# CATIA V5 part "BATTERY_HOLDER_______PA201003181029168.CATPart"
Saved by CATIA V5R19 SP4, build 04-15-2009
Part number: BATTERY_HOLDER_______PA201003181029168
Bounding box of the stored display mesh (mm): x -13 to 13, y -8 to 8, z -29 to 29
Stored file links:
  E:\CadInnWork\1\BATTERY_HOLDER_______PA201003181029168.CATPart
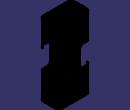
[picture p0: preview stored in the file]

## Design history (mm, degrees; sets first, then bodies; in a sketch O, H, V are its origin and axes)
Parameters
  Update = false
  PDM_version = "A"
  PDM_iteration = 1
  PDM_owner = "moren                    "
  PDM_comment = ""
  PDM_partnumber = "PA002170EA6A57201003181029160008"
Body1 (main body)
  Sketch1 on xy-plane, origin (0, 0, 0), H (1, 0, 0), V (0, 1, 0)
    line L1 (13, 8) -> (13, -8)
    line L2 (13, -8) -> (-13, -8)
    line L3 (-13, -8) -> (-13, 8)
    line L4 (-13, 8) -> (13, 8)
    length L4 = 26
    length L1 = 16
    vertical: L1 V, L3 V
    horizontal: L2 H, L4 H
    equidistance: L1 L3 O, L2 L4 O
  Pad1: profile Sketch1, direction (0, 0, 1), length 29, mirrored extent
  Fillet1: radius 3, on edge [face of Pad1 from Sketch1.L4 | face of Pad1 from Sketch1.L1]; edge [face of Pad1 from Sketch1.L3 | face of Pad1 from Sketch1.L4]; edge [face of Pad1 from Sketch1.L1 | face of Pad1 from Sketch1.L2]; edge [face of Pad1 from Sketch1.L2 | face of Pad1 from Sketch1.L3]
  Sketch2 on xy-plane, origin (0, 0, 0), H (1, 0, 0), V (0, 1, 0)
    line L1 (0.75, 7.25) -> (0.75, -7.25)
    line L2 (0.75, -7.25) -> (10, -7.25)
    line L3 (0.75, 7.25) -> (10, 7.25)
    arc A1 centre (10, 5) radius 2.25 from (10, 7.25) to (12.25, 5) cw
    point P5 (10, 5)
    arc A2 centre (10, -5) radius 2.25 from (10, -7.25) to (12.25, -5) ccw
    reference projected arc E1 centre (10, -5) radius 3 from (10, -8) to (13, -5) ccw from edge [end face of Pad1 | face of Fillet1]
    reference projected arc E2 centre (10, 5) radius 3 from (13, 5) to (10, 8) ccw from edge [end face of Pad1 | face of Fillet1]
    reference intersected line E3 through (0, 0) direction (0, 1) from yz-plane
    reference projected line E4 (13, 8) -> (-13, 8) from edge [face of Pad1 from Sketch1.L4 | end face of Pad1]
    reference projected line E5 (-13, -8) -> (13, -8) from edge [face of Pad1 from Sketch1.L2 | end face of Pad1]
    line L4 (12.25, 5) -> (15.1189, 5)
    line L5 (12.25, -5) -> (15.1189, -5)
    line L6 (15.1189, 5) -> (15.1189, -5)
    reference intersected line E6 through (0, 0) direction (-1, 0) from zx-plane
    distance L1 E3 = 0.75
    distance L3 E4 = 0.75
    distance L2 E5 = 0.75
    vertical: L1 V, L6 V
    horizontal: L2 H, L3 H, L4 H, L5 H
    tangency: A1 L3, A2 L2
    concentricity: E1 A2, A1 E2
    coincidence: L4 P5
    symmetry: L5 L4 E6
  Pocket1: profile Sketch2, direction (0, 0, -1), length 28, mirrored extent
  Mirror1: of Pocket1, about yz-plane
  Sketch3 on zx-plane, origin (0, 0, 0), H (-1, 0, 0), V (0, 0, 1)
    line L1 (7.5, 8) -> (18.3621, 8)
    line L2 (18.3621, 8) -> (18.3621, -8)
    line L3 (18.3621, -8) -> (7.5, -8)
    line L4 (4.5, -5) -> (4.5, 5)
    reference intersected line E1 through (0, 0) direction (-1, 0) from xy-plane
    reference intersected line E2 through (0, 0) direction (0, -1) from yz-plane
    arc A1 centre (7.5, 5) radius 3 from (7.5, 8) to (4.5, 5) ccw
    arc A2 centre (7.5, -5) radius 3 from (4.5, -5) to (7.5, -8) ccw
    distance L4 E2 = 4.5
    length L2 = 16
    radius A1 = 3
    radius A2 = 3
    horizontal: L1 H, L3 H
    vertical: L2 V, L4 V
    symmetry: L3 L1 E1
    tangency: A1 L1, A1 L4, A2 L4, A2 L3
  Pocket2: profile Sketch3, direction (0, -1, 0), through (limit type 3), opposite side through (limit type 3)
  Mirror2: of Pocket2, about yz-plane
  Sketch4 on zx-plane, origin (0, 0, 0), H (-1, 0, 0), V (0, 0, 1)
    line L1 (11.5, 28) -> (16.9342, 28)
    line L2 (16.9342, 28) -> (16.9342, 26)
    line L3 (16.9342, 26) -> (11.5, 26)
    line L4 (11, 26.5) -> (11, 27.5)
    reference intersected line E1 (0.75, 28) -> (15.1189, 28) from face of Mirror1
    reference intersected line E2 through (0, 0) direction (0, -1) from yz-plane
    arc A1 centre (11.5, 27.5) radius 0.5 from (11.5, 28) to (11, 27.5) ccw
    arc A2 centre (11.5, 26.5) radius 0.5 from (11, 26.5) to (11.5, 26) ccw
    distance L4 E2 = 11
    length L2 = 2
    radius A1 = 0.5
    radius A2 = 0.5
    horizontal: L1 H, L3 H
    vertical: L2 V, L4 V
    coincidence: L1 E1
    tangency: A1 L1, A1 L4, A2 L4, A2 L3
  Pocket3: profile Sketch4, direction (0, -1, 0), through (limit type 3), opposite side through (limit type 3)
  Mirror3: of Pocket3, about yz-plane
  Sketch5, origin (0, 0, 0), H (-1, 0, 0), V (0, 0, -1)
    line L1 (11.5, 28) -> (16.9342, 28)
    line L2 (16.9342, 28) -> (16.9342, 26)
    line L3 (16.9342, 26) -> (11.5, 26)
    line L4 (11, 26.5) -> (11, 27.5)
    arc A1 centre (11.5, 27.5) radius 0.5 from (11.5, 28) to (11, 27.5) ccw
    arc A2 centre (11.5, 26.5) radius 0.5 from (11, 26.5) to (11.5, 26) ccw
    length L2 = 2
    radius A1 = 0.5
    radius A2 = 0.5
    horizontal: L1 H, L3 H
    vertical: L2 V, L4 V
    tangency: A1 L1, A1 L4, A2 L4, A2 L3
  Pocket4: profile Sketch5, direction (0, -1, 0), through (limit type 3), opposite side through (limit type 3)
  Mirror4: of Pocket4, about yz-plane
